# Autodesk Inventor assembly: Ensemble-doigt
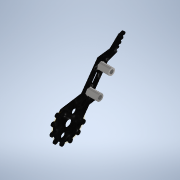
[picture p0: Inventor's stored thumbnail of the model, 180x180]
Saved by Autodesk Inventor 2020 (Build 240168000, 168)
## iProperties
Created: 2021-10
Part Number: Ensemble-doigt
Document SubType Name: Assembly
Designer: bruno
Author: bruno
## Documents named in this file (3)
- C:\Users\bruno\Documents\1-Cours-2021-22\1SI\Challenge-2021\Pince-Inventor\Ensemble-doigt.iam
- C:\Users\bruno\Documents\1-Cours-2021-22\1SI\Challenge-2021\Pince-Inventor\pince.ipt
- C:\Users\bruno\Documents\1-Cours-2021-22\1SI\Challenge-2021\Pince-Inventor\Ecrou-support.ipt
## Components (3 placed, 2 different names)
1. pince:1 — Placage:1, Placage:2, Affleurement:1, Placage:3, Placage:4, Affleurement:2, Placage:5
2. Ecrou-support:1 — Placage:1, Placage:2, Affleurement:1, Placage:3
3. Ecrou-support:2 — Placage:4, Affleurement:2, Placage:5
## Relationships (7: Mate 5, Flush 2)
- Placage:1 [Mate]: pince:1 ↔ Ecrou-support:1
- Placage:2 [Mate]: pince:1 ↔ Ecrou-support:1
- Affleurement:1 [Flush]: pince:1 ↔ Ecrou-support:1
- Placage:3 [Mate]: pince:1 ↔ Ecrou-support:1
- Placage:4 [Mate]: pince:1 ↔ Ecrou-support:2
- Affleurement:2 [Flush]: pince:1 ↔ Ecrou-support:2
- Placage:5 [Mate]: pince:1 ↔ Ecrou-support:2
